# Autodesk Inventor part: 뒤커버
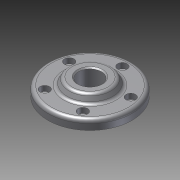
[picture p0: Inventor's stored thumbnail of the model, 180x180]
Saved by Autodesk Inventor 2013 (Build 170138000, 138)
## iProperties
Company: 한국ATC센터
Created: 2014-03
Part Number: 뒤커버
Document SubType Name: Modeling
Designer: KYOUNG IL JANG
Density: 1 g/cm^3
Material: 일반
Author: KYOUNG IL JANG
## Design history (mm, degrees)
sketch "스케치1"
  geometry: C1 r 20 at (0, 0); C2 r 35 at (0, 0); 1 further point
  constraints: 2 centre point, 2 coincident
  dimensions: "d0" = 40 diameter of C1; "d1" = 70 diameter of C2
extrude "돌출1" new body sketch "스케치1" distance "d2" = 5; taper "d3" = 0 deg
extrude "돌출2" join sketch "스케치1" distance "d4" = 8; taper "d5" = 0 deg
sketch "스케치2"
  geometry: C1 r 20 at (0, 0); 1 further point
  constraints: 1 centre point, 1 coincident
  dimensions: "d6" = 40 diameter of C1
extrude "돌출3" join sketch "스케치2" distance "d7" = 6; taper "d8" = -30 deg
sketch "스케치3"
  geometry: 2 further points
  constraints: 1 vertical alignment
  dimensions: "d9" = 27 distance of point (0, 0) point (0, 27)
hole "구멍1" sketch "스케치3" at (0, 27) diameter "d10" = 4.5; stored, may be unused: countersink angle "d14" = 90 deg, drill point angle "d16" = 118 deg; dims "d11" = 6, "d12" = 8, "d13" = 4.4, "d15" = 8
hole "구멍2" diameter "d22" = 19; stored, may be unused: countersink angle "d26" = 90 deg, drill point angle "d28" = 118 deg; dims "d20" = 10, "d21" = 10, "d23" = 6, "d24" = 30, "d25" = 3, "d27" = 8
fillet "모깎기1" dims "d29" = 3
chamfer "모따기1" distance "d30" = 1; stored, may be unused: second distance "d31" = 2, angle "d32" = 45 deg
node "솔리드1"
pattern_circular "원형 패턴1" dims angle "d18" = 360 deg
